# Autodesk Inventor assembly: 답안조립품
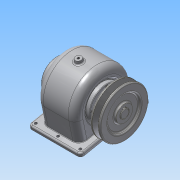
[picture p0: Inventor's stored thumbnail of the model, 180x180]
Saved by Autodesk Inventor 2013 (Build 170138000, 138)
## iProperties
Created: 2015-09
Part Number: 답안조립품
Document SubType Name: Assembly
Designer: Administrator
Author: Administrator
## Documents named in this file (13)
- C:\Users\Administrator\Desktop\450908V1022\답안조립품.iam
- C:\Users\Administrator\Desktop\450908V1022\축.ipt
- C:\Users\Administrator\Desktop\450908V1022\베어링 6203.ipt
- C:\Users\Administrator\Desktop\450908V1022\키 - 6 x 6 x 22.ipt
- C:\Users\Administrator\Desktop\450908V1022\키 - 5 x 5 x 18.ipt
- C:\Users\Administrator\Desktop\450908V1022\스퍼기어.ipt
- C:\Users\Administrator\Desktop\450908V1022\본체.ipt
- C:\Users\Administrator\Desktop\450908V1022\뒤커버.ipt
- C:\Users\Administrator\Desktop\450908V1022\앞커버.ipt
- C:\Users\Administrator\Desktop\450908V1022\볼트 M3 x 8.ipt
- C:\Users\Administrator\Desktop\450908V1022\볼트 M3 x 10.ipt
- C:\Users\Administrator\Desktop\450908V1022\V-벨트풀리.ipt
- C:\Users\Administrator\Desktop\450908V1022\멈춤나사 - M4x10.ipt
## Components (9 placed, 3 different names)
1. V-벨트풀리:1
2. ISO 4762 M3 x 10:1
3. ISO 4762 M3 x 8:1
4. ISO 4762 M3 x 10:2
5. ISO 4762 M3 x 8:2
6. ISO 4762 M3 x 10:3
7. ISO 4762 M3 x 8:3
8. ISO 4762 M3 x 10:4
9. ISO 4762 M3 x 8:4
